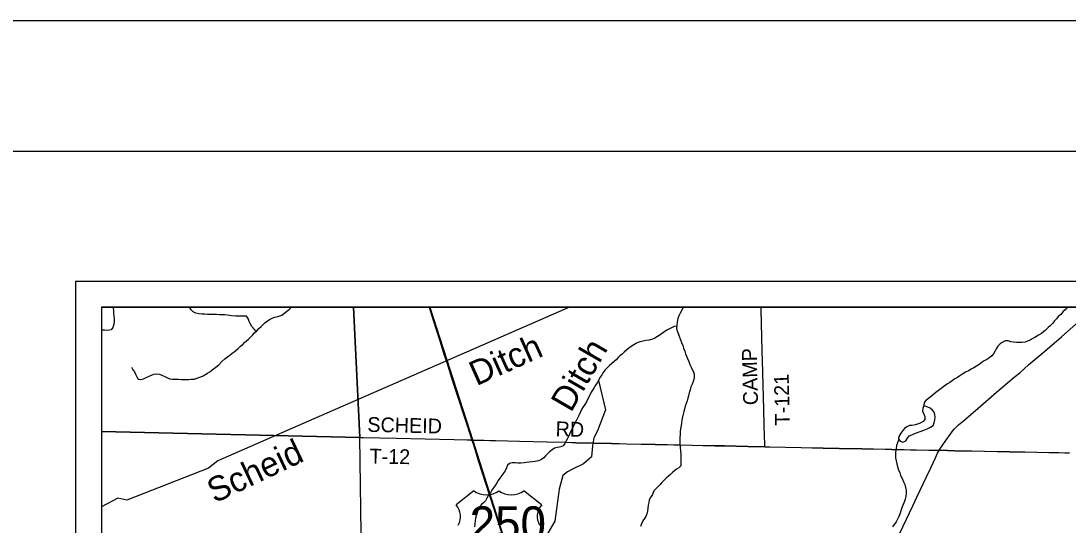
# Model space of a CAD drawing. Extents: x 0 to 34, y 0 to 22.
# Drawn here: x 21.43 to 25.461, y 20.062 to 22 of the extents above; entities that cross this region are included whole.
import ezdxf

# ---------------------------------------------------------------- set-up
doc = ezdxf.new("R2010")
doc.units = 0
for name, color, linetype in [('GM_X_County_Road', 7, 'Continuous'), ('GM_X_Minor_Lake', 7, 'Continuous'), ('GM_X_Minor_River', 7, 'Continuous'), ('GM_X_Minor_River_Text', 7, 'Continuous'), ('GM_X_Rail_Line', 7, 'Continuous'), ('GM_X_Township_Road', 7, 'Continuous'), ('GM_X_Township_Road_Text', 7, 'Continuous'), ('GM_X_US_Location', 7, 'Continuous'), ('GM_X_US_Route', 7, 'Continuous'), ('GM_X_US_Shield', 7, 'Continuous'), ('SH_Border', 7, 'Continuous'), ('SH_Cut_Line', 7, 'Continuous'), ('SH_Data', 7, 'Continuous')]:
    doc.layers.add(name, color=color, linetype=linetype)

msp = doc.modelspace()

# ---------------------------------------------------------------- linework, layer by layer
at = {"layer": 'GM_X_County_Road'}
for points in [[(24.9648, 20.3492), (24.9675, 20.3537), (24.9903, 20.387), (25.0063, 20.41), (25.0157, 20.4223), (25.0236, 20.4318), (25.03, 20.4385), (25.0391, 20.4469), (25.058, 20.4631), (25.1145, 20.5118), (25.1852, 20.5726), (25.2019, 20.5865), (25.228, 20.6086), (25.2515, 20.6286), (25.2584, 20.6339), (25.2749, 20.6477), (25.2914, 20.662), (25.3096, 20.6785), (25.371, 20.731), (25.435, 20.7854), (25.5028, 20.8448), (25.543, 20.8791), (25.5603, 20.894)], [(24.65, 19.7061), (24.6551, 19.7119), (24.661, 19.7192), (24.6663, 19.727), (24.6709, 19.7352), (24.6806, 19.7547), (24.725, 19.8472), (24.7683, 19.9368), (24.8129, 20.0302), (24.8634, 20.136), (24.8791, 20.1695), (24.9162, 20.2475), (24.9322, 20.2812), (24.9504, 20.3207), (24.9584, 20.3376), (24.9627, 20.3458), (24.9648, 20.3492)]]:
    msp.add_lwpolyline(points, dxfattribs=at)
at = {"layer": 'GM_X_Minor_Lake'}
for points in [[(24.9051, 20.5213), (24.9014, 20.5101), (24.9007, 20.4994), (24.9057, 20.4877), (24.9092, 20.4786), (24.9093, 20.4676), (24.9029, 20.4595), (24.8942, 20.4549), (24.8847, 20.4507), (24.8718, 20.4468), (24.8608, 20.4452), (24.8498, 20.4444), (24.8403, 20.4397), (24.8312, 20.4328), (24.8241, 20.4256), (24.8166, 20.4149), (24.8094, 20.4027), (24.8083, 20.3932), (24.8141, 20.3848), (24.8252, 20.3803), (24.8357, 20.3861), (24.8425, 20.3957), (24.8493, 20.4044), (24.8588, 20.4091), (24.8732, 20.4145), (24.8956, 20.4234)], [(24.8956, 20.4234), (24.9057, 20.4269), (24.919, 20.4323), (24.9311, 20.4384), (24.9413, 20.445), (24.9454, 20.4552), (24.9484, 20.4659), (24.9491, 20.4762), (24.9479, 20.4868), (24.9448, 20.4963), (24.939, 20.5039), (24.9295, 20.511), (24.9207, 20.5148), (24.9108, 20.5193), (24.9051, 20.5213)]]:
    msp.add_lwpolyline(points, dxfattribs=at)
at = {"layer": 'GM_X_Minor_River'}
for points in [[(21.7852, 20.9), (21.7855, 20.8959), (21.7862, 20.886), (21.7869, 20.8758), (21.7879, 20.8644), (21.7889, 20.8541), (21.7892, 20.8442), (21.7876, 20.8328), (21.7833, 20.8218), (21.7775, 20.812), (21.7616, 20.8099), (21.7521, 20.8108), (21.7404, 20.8109)], [(23.5414, 20.9), (22.4964, 20.4432), (22.1877, 20.3088), (22.1525, 20.2806), (21.8381, 20.1581), (21.8025, 20.1649), (21.7404, 20.1319)], [(21.8559, 20.6694), (21.8604, 20.6591), (21.8667, 20.6511), (21.8708, 20.6419), (21.876, 20.6312), (21.8809, 20.6228), (21.8923, 20.6208), (21.9014, 20.6238), (21.9102, 20.6282), (21.9231, 20.6346), (21.9327, 20.6383), (21.9418, 20.6416), (21.9536, 20.643), (21.9638, 20.6421), (21.9729, 20.6382), (21.9835, 20.6328), (21.9937, 20.6274), (22.0028, 20.6239), (22.013, 20.6222), (22.0255, 20.6221), (22.0365, 20.6224), (22.0483, 20.6219), (22.0627, 20.6213), (22.076, 20.6216), (22.0859, 20.6226), (22.0977, 20.6233), (22.1076, 20.6262), (22.122, 20.6317), (22.1316, 20.6355), (22.148, 20.6459), (22.1568, 20.6515), (22.1667, 20.6583), (22.1801, 20.6692), (22.1919, 20.6782), (22.2034, 20.6902), (22.2149, 20.7003), (22.2249, 20.7086), (22.2348, 20.715), (22.2429, 20.7221), (22.2513, 20.7277), (22.2589, 20.7337), (22.2658, 20.7409), (22.2758, 20.7499), (22.2838, 20.7563), (22.2907, 20.7634), (22.3056, 20.7769), (22.3133, 20.7837), (22.3213, 20.792), (22.3294, 20.8006), (22.3378, 20.8089), (22.3459, 20.8176), (22.3543, 20.8258), (22.362, 20.8326), (22.3696, 20.8398), (22.378, 20.8457), (22.3872, 20.8525), (22.3967, 20.8573), (22.4078, 20.861), (22.4196, 20.8639), (22.4341, 20.8691), (22.4455, 20.8774), (22.4539, 20.8841), (22.4635, 20.8916), (22.4713, 20.9)], [(22.3351, 20.8063), (22.3295, 20.8143), (22.3194, 20.8247), (22.3119, 20.8362), (22.3082, 20.8449), (22.3049, 20.8564), (22.2981, 20.8644), (22.2883, 20.8653), (22.2776, 20.8654), (22.2666, 20.8648), (22.2567, 20.8645), (22.2404, 20.8665), (22.2249, 20.8682), (22.2146, 20.8695), (22.1942, 20.8704), (22.1824, 20.8709), (22.1706, 20.8718), (22.1592, 20.8708), (22.1478, 20.8709), (22.1365, 20.8722), (22.1262, 20.8727), (22.1145, 20.8739), (22.1035, 20.8759), (22.0929, 20.8814), (22.0854, 20.8898), (22.0789, 20.9)], [(23.9795, 20.9), (23.9782, 20.897), (23.9722, 20.8855), (23.968, 20.8768), (23.9624, 20.8657), (23.9591, 20.8558), (23.9565, 20.8432), (23.9543, 20.8307), (23.9533, 20.8181), (23.9571, 20.8044), (23.961, 20.7957), (23.9656, 20.784), (23.9691, 20.7745), (23.9726, 20.7639), (23.9773, 20.7517), (23.9811, 20.7419), (23.985, 20.7301), (23.9885, 20.7199), (23.9916, 20.7108), (23.9962, 20.7017), (24.0009, 20.6907), (24.0051, 20.6793), (24.0105, 20.6694), (24.0144, 20.6599), (24.0186, 20.6509), (24.021, 20.6414), (24.0214, 20.6269), (24.0181, 20.6143), (24.0133, 20.6033), (24.0088, 20.5938), (24.0058, 20.5823), (24.0028, 20.5698), (23.9999, 20.5591), (23.9977, 20.5496), (23.9943, 20.5389), (23.9902, 20.5286), (23.9872, 20.5183), (23.9843, 20.5077), (23.9813, 20.4982), (23.9787, 20.4879), (23.9761, 20.478), (23.9739, 20.465), (23.9729, 20.4544), (23.971, 20.4437)], [(25.4594, 20.9), (25.4564, 20.8973), (25.4492, 20.8896), (25.4421, 20.8823), (25.4326, 20.8716), (25.4232, 20.8632), (25.416, 20.8548), (25.4089, 20.8468), (25.4002, 20.8368), (25.3919, 20.828), (25.3836, 20.8208), (25.3734, 20.8116), (25.3659, 20.8051), (25.3579, 20.7989), (25.3473, 20.792), (25.3333, 20.7832), (25.3231, 20.7778), (25.3144, 20.7732), (25.3046, 20.7689), (25.2958, 20.7651), (25.2833, 20.7635), (25.2712, 20.7641), (25.2617, 20.7641), (25.2506, 20.7648), (25.2404, 20.7666), (25.2301, 20.7696), (25.2187, 20.7695), (25.2077, 20.7641), (25.1998, 20.758), (25.1903, 20.7492), (25.1843, 20.7389), (25.1783, 20.7293), (25.1735, 20.7198)], [(23.9539, 20.8263), (23.9445, 20.8249), (23.9346, 20.8206), (23.9187, 20.8122), (23.9081, 20.8057), (23.8994, 20.7995), (23.8907, 20.7934), (23.8809, 20.7865), (23.8703, 20.7803), (23.8608, 20.7761), (23.8479, 20.773), (23.835, 20.771), (23.8256, 20.7694), (23.8127, 20.7663), (23.799, 20.7605), (23.7888, 20.7543), (23.7786, 20.7478), (23.7699, 20.7413), (23.762, 20.7359), (23.7518, 20.7267), (23.7438, 20.7191), (23.7355, 20.7122), (23.7294, 20.7057)], [(25.1735, 20.7198), (25.1667, 20.7125), (25.1595, 20.7056), (25.1478, 20.6983), (25.1383, 20.6926), (25.13, 20.6876), (25.122, 20.6822), (25.1077, 20.673), (25.0978, 20.6669), (25.0876, 20.6611), (25.0774, 20.6553), (25.0664, 20.6492), (25.0558, 20.6426), (25.0445, 20.6353), (25.0354, 20.6296), (25.0252, 20.6238), (25.015, 20.6165), (25.0059, 20.6104), (24.9965, 20.6046), (24.984, 20.5954), (24.9757, 20.5897), (24.9666, 20.5828), (24.9568, 20.5755), (24.9454, 20.5663), (24.9349, 20.5578), (24.9235, 20.5486), (24.9145, 20.5414), (24.9069, 20.5326), (24.9051, 20.5212)], [(23.7294, 20.7057), (23.7213, 20.6974), (23.7128, 20.6895), (23.7044, 20.6824), (23.6952, 20.6752), (23.6868, 20.6662), (23.6795, 20.6583), (23.6714, 20.6485), (23.666, 20.6394), (23.6603, 20.63), (23.6537, 20.619), (23.6479, 20.6088), (23.6421, 20.5998), (23.636, 20.5907), (23.6302, 20.5805), (23.6255, 20.5722), (23.6178, 20.5556), (23.6128, 20.5465), (23.607, 20.5359), (23.6004, 20.5257), (23.5942, 20.5159), (23.5881, 20.5057), (23.5842, 20.497), (23.5788, 20.4857), (23.5734, 20.4754), (23.5687, 20.4652), (23.5641, 20.4565), (23.5594, 20.4471), (23.5532, 20.4354), (23.5482, 20.4252), (23.5435, 20.4142), (23.5389, 20.4051), (23.5339, 20.3941), (23.5292, 20.3854), (23.5242, 20.376), (23.5169, 20.3666), (23.5078, 20.3625), (23.4956, 20.3603), (23.4838, 20.357), (23.475, 20.3514), (23.4651, 20.3435), (23.4566, 20.3356), (23.4493, 20.3277), (23.4428, 20.3198), (23.4344, 20.3135), (23.4218, 20.3083), (23.41, 20.3065), (23.3975, 20.3051), (23.3865, 20.3041), (23.3766, 20.3026), (23.3667, 20.3016), (23.3542, 20.3002), (23.3432, 20.2999), (23.3337, 20.3004), (23.3215, 20.3009), (23.3113, 20.2991), (23.3028, 20.292), (23.299, 20.2818), (23.2935, 20.2708), (23.2862, 20.2602), (23.2808, 20.2519), (23.2731, 20.2418), (23.2674, 20.2335), (23.2616, 20.2244), (23.2554, 20.2134), (23.2492, 20.2048), (23.2431, 20.1965), (23.2373, 20.1863), (23.2296, 20.1765), (23.2238, 20.1651), (23.2188, 20.1545), (23.2111, 20.1474), (23.2035, 20.1414), (23.1966, 20.1335), (23.1904, 20.1233), (23.1873, 20.113), (23.1833, 20.1009), (23.1802, 20.088), (23.179, 20.0785), (23.1777, 20.0656), (23.1757, 20.055)], [(23.6532, 20.6181), (23.6807, 20.5051), (23.6499, 20.4245), (23.6349, 20.3969), (23.6304, 20.3665), (23.6258, 20.324), (23.5952, 20.2966), (23.5555, 20.2784), (23.5334, 20.2664), (23.5162, 20.2522), (23.502, 20.1999), (23.4857, 20.0765), (23.4583, 20.0312)], [(23.971, 20.4437), (23.9692, 20.4319), (23.9678, 20.4216), (23.9671, 20.4106), (23.9668, 20.3981), (23.9665, 20.3848), (23.967, 20.3737), (23.9675, 20.36), (23.9691, 20.3475), (23.9703, 20.3335), (23.9708, 20.3205), (23.9702, 20.3), (23.9706, 20.2901), (23.9631, 20.2817), (23.954, 20.2767), (23.9453, 20.2698), (23.9377, 20.2633), (23.9302, 20.2568), (23.923, 20.2503), (23.9136, 20.2422), (23.9045, 20.2334), (23.8962, 20.2242), (23.8891, 20.2158), (23.8819, 20.2093), (23.8743, 20.2009), (23.8668, 20.1933), (23.8608, 20.1792), (23.8537, 20.1681), (23.848, 20.1585), (23.8466, 20.149), (23.8451, 20.138), (23.8437, 20.1262), (23.8419, 20.1148), (23.8397, 20.1053), (23.8352, 20.0953), (23.8299, 20.0869), (23.8235, 20.0774), (23.8187, 20.0663), (23.8149, 20.0557)], [(24.8097, 20.3911), (24.8039, 20.3783), (24.8009, 20.3673), (24.7987, 20.3543), (24.7969, 20.3414), (24.7962, 20.3311), (24.7971, 20.3197), (24.7991, 20.3083), (24.8018, 20.2973), (24.8042, 20.2859), (24.8084, 20.2738), (24.8127, 20.2632), (24.8158, 20.2525), (24.8231, 20.2381), (24.8277, 20.2283), (24.8327, 20.2173), (24.8355, 20.2067), (24.8375, 20.1945), (24.8379, 20.1839), (24.8369, 20.1721), (24.8343, 20.161), (24.8298, 20.1496), (24.8261, 20.1404), (24.8227, 20.1313), (24.8182, 20.1202), (24.8145, 20.1069), (24.8089, 20.0943), (24.8044, 20.0844), (24.7992, 20.0737), (24.7852, 20.0546)]]:
    msp.add_lwpolyline(points, dxfattribs=at)
at = {"layer": 'GM_X_Rail_Line'}
for points in [[(22.7105, 20.9), (21.7404, 20.9), (21.7404, 20.4215), (22.7344, 20.3983)], [(21.7404, 20.4215), (21.7404, 15.3991), (21.8438, 15.3957), (22.1541, 15.3939), (22.7997, 15.3881), (22.8171, 15.3878), (22.7976, 16.0573), (22.7976, 16.0673), (22.7968, 16.0986), (22.7971, 16.1327), (22.7975, 16.1451), (22.7983, 16.1543), (22.7997, 16.1635), (22.8011, 16.1695), (22.8022, 16.174), (22.7889, 17.0447), (22.7764, 17.8836), (22.7682, 18.2341), (22.7679, 18.2482), (22.7589, 18.6495), (22.7344, 20.3983)]]:
    msp.add_lwpolyline(points, close=True, dxfattribs=at)
for points in [[(28.5404, 20.9), (22.7105, 20.9), (22.7344, 20.3983), (22.7469, 20.3982), (22.8122, 20.3968), (22.8745, 20.3956), (23.0972, 20.3907), (23.148, 20.3896), (23.1619, 20.3892), (23.1656, 20.3891), (23.3026, 20.3856), (23.3492, 20.3848), (23.4549, 20.3822), (23.5295, 20.3805), (23.5666, 20.3789), (23.7034, 20.3761), (23.7624, 20.3747), (23.8712, 20.3722), (24.0142, 20.369), (24.0546, 20.3682), (24.1012, 20.3673), (24.1385, 20.3671), (24.2286, 20.3649), (24.2937, 20.3635), (24.3125, 20.3631), (24.4338, 20.3605), (24.5177, 20.3584), (24.5799, 20.3572), (24.6669, 20.3556), (24.757, 20.3536), (24.7819, 20.3531), (24.9249, 20.3503), (24.9646, 20.3498), (24.9684, 20.3498), (24.9963, 20.3493), (25.0242, 20.3483), (25.0895, 20.3472), (25.1391, 20.3463), (25.2353, 20.3444), (25.2943, 20.3434), (25.3866, 20.3413), (25.4021, 20.3414), (25.4477, 20.3398), (25.4567, 20.34), (25.4658, 20.3404)], [(23.0044, 20.9), (23.1694, 20.3875), (23.6827, 18.7751), (23.7208, 18.6568), (23.763, 18.5542), (23.8134, 18.4649), (23.9534, 18.2458)]]:
    msp.add_lwpolyline(points, dxfattribs=at)
at = {"layer": 'GM_X_Township_Road'}
for points in [[(24.2939, 20.363), (24.2936, 20.3719), (24.2916, 20.4434), (24.2896, 20.5055), (24.2847, 20.695), (24.2839, 20.7292), (24.2811, 20.8379), (24.2799, 20.8876), (24.2795, 20.9)], [(23.0974, 20.3902), (23.1482, 20.3891), (23.1621, 20.3887), (23.1658, 20.3886)], [(23.1658, 20.3886), (23.3028, 20.385), (23.3494, 20.3842), (23.4551, 20.3816), (23.5297, 20.3799), (23.5669, 20.3784), (23.7036, 20.3755), (23.7626, 20.3741), (23.8714, 20.3716), (24.0144, 20.3685), (24.0548, 20.3677), (24.1014, 20.3667), (24.1387, 20.3666), (24.2288, 20.3643), (24.2939, 20.363)], [(24.2939, 20.363), (24.3128, 20.3626), (24.434, 20.36), (24.5179, 20.3579), (24.5801, 20.3566), (24.6671, 20.3551), (24.7573, 20.3531), (24.7821, 20.3525), (24.9251, 20.3498), (24.9648, 20.3492)], [(24.9648, 20.3492), (24.9686, 20.3492), (24.9965, 20.3487), (25.0244, 20.3478), (25.0897, 20.3467), (25.1393, 20.3457), (25.2355, 20.3439), (25.2946, 20.3429), (25.3869, 20.3408), (25.4023, 20.3409), (25.4479, 20.3393), (25.4569, 20.3394), (25.466, 20.3398)]]:
    msp.add_lwpolyline(points, dxfattribs=at)
at = {"layer": 'GM_X_US_Route'}
for points in [[(23.0011, 20.9), (23.0175, 20.8491), (23.0436, 20.7667), (23.0583, 20.7192), (23.069, 20.6867), (23.0873, 20.6273), (23.099, 20.5919), (23.1474, 20.4443), (23.1658, 20.3886)], [(23.1658, 20.3886), (23.1732, 20.3658), (23.1905, 20.3106), (23.234, 20.1753), (23.2679, 20.0686), (23.3476, 19.8161), (23.3801, 19.7161), (23.4009, 19.6509), (23.4481, 19.5058), (23.4704, 19.4369), (23.4816, 19.3998), (23.5363, 19.2274), (23.6016, 19.0231), (23.6641, 18.8276), (23.6786, 18.7833), (23.6875, 18.7578)]]:
    msp.add_lwpolyline(points, dxfattribs=at)
at = {"layer": 'GM_X_US_Shield'}
for p, q in [((23.1736, 20.194), (23.1049, 20.139)), ((23.4345, 20.139), (23.3658, 20.194))]:
    msp.add_line(p, q, dxfattribs=at)
for centre, major_axis, start_param, end_param in [((23.2217, 20.2332), (-0.0687, 0), 0.795399, 2.346194), ((23.3178, 20.2332), (-0.0687, 0), 0.795399, 2.346194), ((23.0262, 20.0949), (0.0961, 0), 5.838949, 6.894067), ((23.5133, 20.0949), (-0.0961, 0), 5.672304, 6.727422)]:
    msp.add_ellipse(centre, major_axis=major_axis, ratio=0.8, start_param=start_param, end_param=end_param, dxfattribs=at)
at = {"layer": 'SH_Border'}
msp.add_lwpolyline([(1.5, 21.5), (33.5, 21.5), (33.5, 0.5), (1.5, 0.5)], close=True, dxfattribs=at)
at = {"layer": 'SH_Cut_Line'}
msp.add_lwpolyline([(0, 0), (34, 0), (34, 22), (0, 22)], close=True, dxfattribs=at)
msp.add_lwpolyline([(28.5404, 15.3151), (28.5404, 20.9), (21.7404, 20.9), (21.7404, 15.3991)], dxfattribs=at)
at = {"layer": 'SH_Data'}
for p, q in [((21.6404, 21), (28.6404, 21)), ((21.6404, 21), (21.6404, 14)), ((21.7404, 20.9), (21.7404, 14.1)), ((21.7404, 20.9), (28.5404, 20.9))]:
    msp.add_line(p, q, dxfattribs=at)

# ---------------------------------------------------------------- texts
at = {"layer": 'GM_X_Minor_River_Text'}
for s, rotation, p in [('Ditch', 24.218, (23.1833, 20.5954)), ('Ditch', 59.9675, (23.5473, 20.4914)), ('Scheid', 25.3351, (22.1756, 20.1442))]:
    msp.add_text(s, height=0.09475, rotation=rotation, dxfattribs=at).set_placement(p)
at = {"layer": 'GM_X_Township_Road_Text'}
for s, rotation, p in [('CAMP', 91.4565, (24.2675, 20.5233)), ('T-121', 91.3975, (24.3901, 20.4454)), ('SCHEID', 358.6724, (22.7631, 20.4204)), ('RD', 358.5195, (23.4876, 20.4037)), ('T-12', 358.945, (22.7717, 20.2986))]:
    msp.add_text(s, height=0.05682, rotation=rotation, dxfattribs=at).set_placement(p)
at = {"layer": 'GM_X_US_Location'}
for s in ['0', '/']:
    msp.add_text(s, height=0.000189, dxfattribs=at).set_placement((23.2698, 20.0675))
at = {"layer": 'GM_X_US_Shield'}
msp.add_text('250', height=0.13184, dxfattribs=at).set_placement((23.157, 20.0017))

doc.saveas('drawing.dxf')
